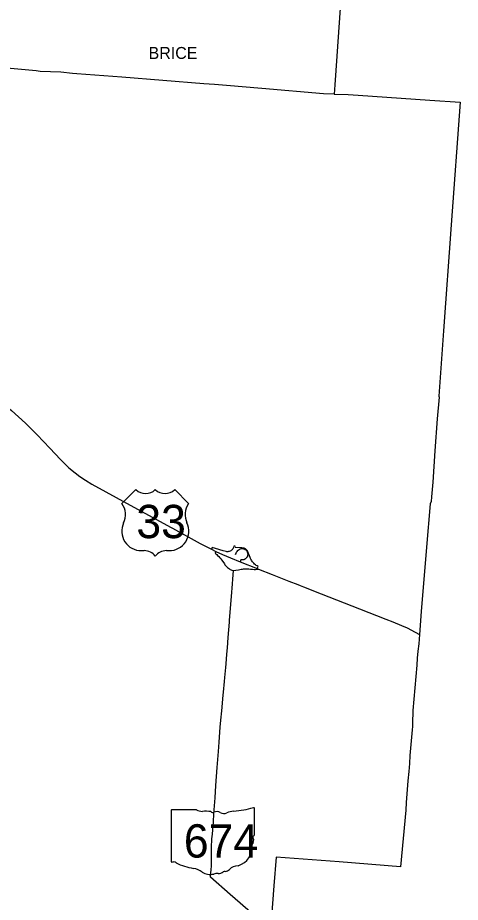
# Model space of a CAD drawing. Extents: x -1146 to -445, y -1283 to -822.
# Drawn here: x -786.6 to -740.3, y -1188.9 to -1096.4 of the extents above; entities that cross this region are included whole.
import ezdxf

# ---------------------------------------------------------------- set-up
doc = ezdxf.new("R2010")
doc.units = 0
for name, color, linetype in [('GM_X_Corporation_Text', 7, 'Continuous'), ('GM_X_County', 7, 'Continuous'), ('GM_X_Interchange_Ramps', 7, 'Continuous'), ('GM_X_State_Route', 7, 'Continuous'), ('GM_X_State_Shield', 7, 'Continuous'), ('GM_X_Township', 7, 'Continuous'), ('GM_X_US_Route', 7, 'Continuous'), ('GM_X_US_Shield', 7, 'Continuous')]:
    doc.layers.add(name, color=color, linetype=linetype)

msp = doc.modelspace()

# ---------------------------------------------------------------- linework, layer by layer
at = {"layer": 'GM_X_County'}
msp.add_lwpolyline([(-752.566, -1090.897), (-753.436, -1103.447), (-753.503, -1104.417), (-752.059, -1104.446), (-751.005, -1104.51), (-743.508, -1105.03), (-740.333, -1105.239), (-741.283, -1118.091), (-742.101, -1129.161), (-742.564, -1135.979), (-742.557, -1136.109), (-742.735, -1138.372), (-742.98, -1141.69), (-743.217, -1144.978), (-743.338, -1146.52), (-743.394, -1147.008), (-743.48, -1147.242), (-743.86, -1151.765), (-744.407, -1158.508), (-744.612, -1160.916), (-744.674, -1161.875), (-744.757, -1162.636), (-744.825, -1163.394), (-744.863, -1164.12), (-745.28, -1168.857), (-745.336, -1170.219), (-745.317, -1170.321), (-745.334, -1170.532), (-745.363, -1170.887), (-745.594, -1173.572), (-745.657, -1174.399), (-745.724, -1175.238), (-745.805, -1176.194), (-745.995, -1178.476), (-746.033, -1179.273), (-746.575, -1185.192), (-752.983, -1184.688), (-759.584, -1184.205), (-759.815, -1187.188), (-760.095, -1190.896)], dxfattribs=at)
at = {"layer": 'GM_X_Interchange_Ramps'}
for points in [[(-763.844, -1151.688), (-763.994, -1151.679), (-764.045, -1151.826), (-764.084, -1151.906), (-764.131, -1151.977), (-764.187, -1152.042), (-764.255, -1152.104), (-764.318, -1152.148), (-764.396, -1152.191), (-764.492, -1152.227), (-764.569, -1152.244), (-764.643, -1152.253), (-764.721, -1152.254), (-764.814, -1152.243), (-765.109, -1152.167), (-765.922, -1151.915), (-766.248, -1151.796), (-766.341, -1152.001)], [(-765.885, -1152.226), (-765.965, -1152.405), (-765.896, -1152.457), (-765.793, -1152.543), (-765.693, -1152.633), (-765.578, -1152.747), (-765.461, -1152.875), (-765.363, -1152.996), (-765.267, -1153.126), (-764.983, -1153.536), (-764.923, -1153.621), (-764.845, -1153.718), (-764.764, -1153.802), (-764.67, -1153.886), (-764.554, -1153.971), (-764.457, -1154.046), (-764.366, -1154.106), (-764.283, -1154.15), (-764.209, -1154.19), (-764.041, -1154.227)], [(-763.901, -1152.49), (-763.796, -1152.499), (-763.75, -1152.387), (-763.713, -1152.315), (-763.656, -1152.22), (-763.593, -1152.136), (-763.534, -1152.074), (-763.441, -1152.006), (-763.337, -1151.957), (-763.225, -1151.929), (-763.107, -1151.923), (-762.999, -1151.938), (-762.909, -1151.968), (-762.823, -1152.012), (-762.756, -1152.061), (-762.687, -1152.128), (-762.635, -1152.199), (-762.598, -1152.266), (-762.564, -1152.36), (-762.546, -1152.457), (-762.543, -1152.55), (-762.555, -1152.639), (-762.58, -1152.725), (-762.617, -1152.805), (-762.662, -1152.874), (-762.72, -1152.94), (-762.794, -1153.002), (-762.881, -1153.053), (-762.967, -1153.086), (-763.056, -1153.106), (-763.186, -1153.109), (-763.254, -1153.095), (-763.343, -1153.305)], [(-761.548, -1154.019), (-761.456, -1153.815), (-761.57, -1153.742), (-761.666, -1153.677), (-761.75, -1153.611), (-761.826, -1153.545), (-761.913, -1153.459), (-761.996, -1153.366), (-762.052, -1153.295), (-762.11, -1153.213), (-762.161, -1153.132), (-762.216, -1153.033), (-762.256, -1152.95), (-762.289, -1152.872), (-762.531, -1152.271), (-762.579, -1152.176), (-762.645, -1152.086), (-762.706, -1152.024), (-762.79, -1151.963), (-762.859, -1151.925), (-762.931, -1151.896), (-763.027, -1151.872), (-763.16, -1151.843), (-763.786, -1151.805), (-763.85, -1151.8)]]:
    msp.add_lwpolyline(points, dxfattribs=at)
at = {"layer": 'GM_X_State_Route'}
for points in [[(-764.107, -1155.127), (-764.041, -1154.227)], [(-764.041, -1154.227), (-763.779, -1154.186), (-763.497, -1154.137), (-763.248, -1154.09), (-763.104, -1154.069), (-762.975, -1154.052), (-762.811, -1154.043), (-762.613, -1154.04), (-762.415, -1154.05), (-762.242, -1154.063), (-762.041, -1154.092), (-761.868, -1154.123), (-761.722, -1154.123), (-761.422, -1154.07)], [(-764.453, -1159.452), (-764.345, -1158.143), (-764.247, -1156.928), (-764.143, -1155.608), (-764.107, -1155.127)], [(-764.842, -1164.37), (-764.795, -1163.969), (-764.722, -1162.957), (-764.667, -1162.309), (-764.597, -1161.23), (-764.466, -1159.617), (-764.453, -1159.452)], [(-764.974, -1165.811), (-764.936, -1165.419), (-764.842, -1164.37)], [(-766.338, -1183.787), (-766.341, -1183.679), (-766.345, -1183.214), (-766.337, -1182.992), (-766.327, -1182.816), (-766.314, -1182.611), (-766.282, -1182.264), (-766.233, -1181.789), (-766.134, -1180.482), (-766.078, -1179.675), (-765.951, -1177.994), (-765.867, -1176.68), (-765.742, -1174.799), (-765.617, -1173.154), (-765.535, -1172.178), (-765.411, -1170.596), (-765.342, -1169.853), (-765.258, -1168.9), (-765.107, -1167.259), (-765.082, -1166.944), (-764.974, -1165.811)], [(-766.368, -1185.496), (-766.367, -1185.489), (-766.342, -1185.123), (-766.325, -1184.753), (-766.323, -1184.451), (-766.338, -1183.787)], [(-766.442, -1186.283), (-766.442, -1186.283), (-766.368, -1185.496)], [(-760.162, -1191.84), (-760.969, -1191.063), (-761.529, -1190.551), (-761.975, -1190.169), (-762.009, -1190.141), (-764.369, -1188.098), (-766.442, -1186.283)]]:
    msp.add_lwpolyline(points, dxfattribs=at)
at = {"layer": 'GM_X_State_Shield'}
for p, q in [((-767.917, -1179.23), (-770.465, -1179.23)), ((-761.849, -1181.863), (-761.849, -1179.099)), ((-770.55, -1179.321), (-770.55, -1184.604)), ((-761.85, -1181.862), (-761.849, -1181.863))]:
    msp.add_line(p, q, dxfattribs=at)
for centre, major_axis, start_param, end_param in [((-770.451, -1179.31), (0.101, 0), 1.712693, 3.28349), ((-767.31, -1178.617), (0.978, 0), 4.042523, 4.731795), ((-764.949, -1172.027), (9.227, 0), 4.814394, 5.042369), ((-761.946, -1179.088), (0.0969, 0), 6.141152, 7.989035), ((-766.986, -1182.196), (3.51, 0), 1.404758, 1.657858), ((-766.189, -1179.282), (0.282, 0), 3.836095, 5.185415), ((-765.775, -1179.893), (0.586, 0), 0.950623, 2.079405), ((-765.018, -1179.056), (0.705, 0), 4.081561, 5.145723), ((-763.772, -1180.844), (1.856, 0), 1.699011, 2.107814), ((-761.872, -1182.066), (0.15, 0), 1.883978, 3.671073), ((-761.953, -1181.874), (0.104, 0), 5.05454, 6.418171), ((-761.502, -1183.02), (0.655, 0), 2.387724, 3.262537), ((-762.825, -1182.415), (0.9, 0), 5.934695, 6.695948), ((-764.432, -1183.371), (2.308, 0), 5.101752, 6.440018), ((-770.45, -1184.616), (0.102, 0), 3.00124, 4.508301), ((-770.434, -1184.075), (0.776, 0), 4.665946, 4.897461), ((-770.276, -1184.909), (0.28, 0), 0.519207, 1.627899), ((-766.743, -1180.162), (6.663, 0), 4.195997, 4.488961), ((-768.729, -1186.978), (2.085, 0), 0.823519, 1.323587), ((-766.474, -1184.935), (1.323, 0), 4.026481, 4.996735), ((-765.613, -1185.331), (0.705, 0), 4.691044, 5.507374), ((-764.976, -1185.843), (0.198, 0), 1.147584, 2.315152), ((-765.06, -1185.116), (0.746, 0), 4.937069, 5.64225), ((-763.459, -1186.088), (1.264, 0), 1.647645, 2.488434), ((-765.71, -1186.762), (1.087, 0), 1.495662, 1.94098)]:
    msp.add_ellipse(centre, major_axis=major_axis, ratio=0.8, start_param=start_param, end_param=end_param, dxfattribs=at)
at = {"layer": 'GM_X_Township'}
msp.add_lwpolyline([(-753.498, -1104.346), (-753.503, -1104.417), (-754.619, -1104.36), (-761.084, -1103.813), (-764.758, -1103.512), (-766.027, -1103.414), (-767.119, -1103.327), (-775.717, -1102.639), (-780.402, -1102.275), (-780.847, -1102.238), (-782.082, -1102.123), (-784.238, -1102.028), (-784.642, -1101.989), (-788.532, -1101.616)], dxfattribs=at)
at = {"layer": 'GM_X_US_Route'}
for points in [[(-796.265, -1129.799), (-794.971, -1130.905), (-792.364, -1133.132), (-790.065, -1135.107), (-789.806, -1135.34), (-789.528, -1135.577), (-788.145, -1136.739), (-787.251, -1137.502), (-785.769, -1138.82), (-785.123, -1139.466), (-784.543, -1140.047), (-783.239, -1141.424), (-782.129, -1142.603), (-781.234, -1143.468), (-780.589, -1143.995), (-780.079, -1144.379), (-779.517, -1144.768), (-778.842, -1145.18), (-774.819, -1147.381), (-770.552, -1149.725), (-770.424, -1149.795)], [(-770.424, -1149.795), (-767.531, -1151.376), (-766.341, -1152.001), (-765.885, -1152.226), (-765.201, -1152.543), (-763.938, -1153.066)], [(-763.938, -1153.066), (-763.739, -1153.146)], [(-763.739, -1153.146), (-763.343, -1153.305), (-761.548, -1154.019), (-761.422, -1154.07)], [(-761.422, -1154.07), (-759.978, -1154.627), (-758.246, -1155.316), (-757.32, -1155.677), (-757.317, -1155.679)], [(-757.317, -1155.679), (-757.067, -1155.774)], [(-757.067, -1155.774), (-756.703, -1155.913), (-754.872, -1156.648), (-750.861, -1158.223), (-748.119, -1159.308), (-747.374, -1159.6), (-746.46, -1159.955), (-745.889, -1160.22), (-745.041, -1160.665), (-744.612, -1160.916)]]:
    msp.add_lwpolyline(points, dxfattribs=at)
at = {"layer": 'GM_X_US_Shield'}
for p, q in [((-774.237, -1145.758), (-775.687, -1147.209)), ((-768.726, -1147.209), (-770.177, -1145.758)), ((-773.657, -1152.139), (-773.367, -1152.139)), ((-771.047, -1152.139), (-770.757, -1152.139))]:
    msp.add_line(p, q, dxfattribs=at)
for centre, radius, start, end in [((-773.222, -1144.723), 1.45, 225.573, 314.427), ((-771.192, -1144.723), 1.45, 225.573, 314.427), ((-777.351, -1148.373), 2.03, 334.54712, 35.00093), ((-767.063, -1148.373), 2.03, 144.99907, 205.45288), ((-773.68, -1150.109), 2.03, 154.83192, 270.63826), ((-770.734, -1150.109), 2.03, 269.36174, 25.16808), ((-773.367, -1153.59), 1.45, 36.8699, 90), ((-771.047, -1153.59), 1.45, 90, 143.1301)]:
    msp.add_arc(centre, radius, start, end, dxfattribs=at)

# ---------------------------------------------------------------- texts
at = {"layer": 'GM_X_Corporation_Text'}
msp.add_text('BRICE', height=1.25, rotation=0.00001, dxfattribs=at).set_placement((-772.909, -1100.729))
at = {"layer": 'GM_X_State_Shield'}
msp.add_text('674', height=3.4805, dxfattribs=at).set_placement((-769.222, -1184.232))
at = {"layer": 'GM_X_US_Shield'}
msp.add_text('33', height=3.4805, dxfattribs=at).set_placement((-774.188, -1150.834))

doc.saveas('drawing.dxf')
